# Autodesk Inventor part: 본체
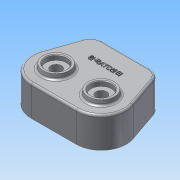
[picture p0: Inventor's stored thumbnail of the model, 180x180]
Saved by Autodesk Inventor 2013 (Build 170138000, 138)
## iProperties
Created: 2014-12
Part Number: 본체
Material: 알루미늄 6061
Document SubType Name: Modeling
Designer: Administrator
Density: 2.71 g/cm^3
Mass: 612.316 g
Surface Area: 666.735 cm^2
Volume: 225.947 cm^3
Author: Administrator
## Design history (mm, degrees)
sketch "스케치1"
  geometry: L1 (-47, 36)-(47, 36); L2 (47, 36)-(66.565, -20.803); L3 (32.527, -68.527)-(-32.527, -68.527); L4 (-66.565, -20.803)-(-47, 36); L5 (0, 0)-(-32.527, -32.527); L6 (0, 0)-(32.527, -32.527); A1 r 36 centre (-32.527, -32.527) between (-66.565, -20.803) and (-32.527, -68.527); A2 r 36 centre (32.527, -32.527) between (32.527, -68.527) and (66.565, -20.803); 2 further points
  constraints: 12 end point, 4 point on circle, 4 tangent, 2 centre point, 2 midpoint, 2 perpendicular, 2 vertical alignment, 1 horizontal, 1 parallel
  dimensions: "d0" = 94 distance of L1.start L1.end; "d89" = 72 diameter of A1; "d90" = 72 diameter of A2; "d91" = 36 distance from line of L1 L5.start; "d92" = 46 distance of L5.start L5.end
extrude "돌출1" new body sketch "스케치1" distance "d30" = 44; taper "d31" = 0 deg
fillet "모깎기2" dims "d33" = 18
sketch "스케치13"
  geometry: L1 (-34.162, 36)-(34.162, 36) reference; L2 (51.181, 23.862)-(66.565, -20.803) reference; L3 (-66.565, -20.803)-(-51.181, 23.862) reference; L4 (-34.162, 36)-(34.162, 36) reference; L5 (32.527, -68.527)-(-32.527, -68.527) reference; A1 r 18 centre (-34.162, 18) between (-34.162, 36) and (-51.181, 23.862) reference; A2 r 18 centre (34.162, 18) between (51.181, 23.862) and (34.162, 36) reference; A3 r 36 centre (32.527, -32.527) between (32.527, -68.527) and (66.565, -20.803) reference; A4 r 36 centre (-32.527, -32.527) between (-66.565, -20.803) and (-32.527, -68.527) reference; 2 further points
  constraints: 1 vertical alignment, 1 other
  dimensions: "d86" = 30 distance from line of L1 point (0, 6)
feature "엠보싱1" sketch "스케치13" dims "d0" = 94, "d87" = 1, "d88" = 0, "d89" = 72, "d90" = 72, "d91" = 36, "d92" = 46
sketch "스케치14"
  geometry: L1 (-51.181, 23.862)-(-66.565, -20.803) reference; L2 (-32.527, -68.527)-(32.527, -68.527) reference; L3 (66.565, -20.803)-(51.181, 23.862) reference; L4 (34.162, 36)-(-34.162, 36) reference; L5 (-46.453, 22.233)-(-61.837, -22.432); L6 (-32.527, -63.527)-(32.527, -63.527); L7 (61.837, -22.432)-(46.453, 22.233); L8 (34.162, 31)-(-34.162, 31); A1 r 18 centre (-34.162, 18) between (-34.162, 36) and (-51.181, 23.862) reference; A2 r 36 centre (-32.527, -32.527) between (-66.565, -20.803) and (-32.527, -68.527) reference; A3 r 36 centre (32.527, -32.527) between (32.527, -68.527) and (66.565, -20.803) reference; A4 r 18 centre (34.162, 18) between (51.181, 23.862) and (34.162, 36) reference; A5 r 13 centre (-34.162, 18) between (-34.162, 31) and (-46.453, 22.233); A6 r 31 centre (-32.527, -32.527) between (-61.837, -22.432) and (-32.527, -63.527); A7 r 31 centre (32.527, -32.527) between (32.527, -63.527) and (61.837, -22.432); A8 r 13 centre (34.162, 18) between (46.453, 22.233) and (34.162, 31); 1 further point
  constraints: 8 end point, 8 point on circle, 4 centre point, 7 other
  dimensions: "d93" = 5 distance between parallel lines of L4 L8
extrude "돌출8" cut sketch "스케치14" distance "d94" = 34; taper "d95" = 0 deg
sketch "스케치15"
  geometry: C1 r 24 at (0, 0); C2 r 24 at (-32.527, -32.527); C3 r 24 at (32.527, -32.527); A1 r 31 centre (-32.527, -32.527) between (-61.837, -22.432) and (-32.527, -63.527) reference; A2 r 31 centre (32.527, -32.527) between (32.527, -63.527) and (61.837, -22.432) reference; 1 further point
  constraints: 3 centre point, 3 coincident
  dimensions: "d96" = 48 diameter of C1; "d97" = 48 diameter of C2; "d98" = 48 diameter of C3
extrude "돌출9" join sketch "스케치15" distance "d99" = 11; taper "d100" = 0 deg
sketch "스케치16"
  geometry: C1 r 20 at (0, 0); A1 r 24 centre (0, 0) between (21.111, -11.416) and (-21.111, -11.416) reference
  constraints: 1 centre point, 1 coincident
  dimensions: "d101" = 40 diameter of C1
extrude "돌출10" cut sketch "스케치16" distance "d102" = 12; taper "d103" = 0 deg
sketch "스케치17"
  geometry: C1 r 20 at (0, 0) reference; C2 r 10 at (0, 0)
  constraints: 1 centre point, 1 coincident
  dimensions: "d104" = 20 diameter of C2
extrude "돌출11" cut sketch "스케치17" distance "d105" = 3; taper "d106" = 0 deg
sketch "스케치18"
  geometry: C1 r 20 at (0, 0) reference; C2 r 17.5 at (-32.527, -32.527); C3 r 17.5 at (32.527, -32.527); A1 r 24 centre (0, 0) between (-11.416, -21.111) and (11.416, -21.111) reference; A2 r 24 centre (32.527, -32.527) between (11.416, -21.111) and (21.111, -11.416) reference; A3 r 24 centre (0, 0) between (21.111, -11.416) and (-21.111, -11.416) reference; A4 r 24 centre (-32.527, -32.527) between (-21.111, -11.416) and (-11.416, -21.111) reference
  constraints: 2 centre point, 2 coincident
  dimensions: "d107" = 35 diameter of C2; "d108" = 35 diameter of C3
extrude "돌출12" cut sketch "스케치18" distance "d109" = 11; taper "d110" = 0 deg
sketch "스케치19"
  geometry: C1 r 20 at (-32.527, -32.527); C2 r 20 at (32.527, -32.527); A1 r 36 centre (-32.527, -32.527) between (-66.565, -20.803) and (-32.527, -68.527) reference; A2 r 36 centre (32.527, -32.527) between (32.527, -68.527) and (66.565, -20.803) reference; 1 further point
  constraints: 2 centre point, 2 coincident
  dimensions: "d111" = 40 diameter of C1; "d112" = 40 diameter of C2
extrude "돌출13" join sketch "스케치19" distance "d113" = 7; taper "d114" = -10 deg
sketch "스케치20"
  geometry: C1 r 18.766 at (0, 0) reference; C2 r 18.766 at (65.054, 0) reference; 3 further points
  constraints: 2 coincident
hole "구멍4" sketch "스케치20" at (0, 0), (65.054, 0) diameter "d115" = 15.5; stored, may be unused: countersink angle "d119" = 90 deg, drill point angle "d121" = 118 deg; dims "d116" = 20, "d117" = 30, "d118" = 7, "d120" = 23
sketch "스케치21"
  geometry: L1 (-61.837, -22.432)-(-46.453, 22.233) reference; L2 (46.453, 22.233)-(61.837, -22.432) reference; L3 (32.527, -63.527)-(-32.527, -63.527) reference; L4 (34.162, 36)-(-34.162, 36) reference; A1 r 8 centre (-51.7, 7) between (-54.305, -0.564) and (-49.095, 14.564); A2 r 8 centre (51.7, 7) between (49.095, 14.564) and (54.305, -0.564); A3 r 8 centre (0, -63.527) between (8, -63.527) and (-8, -63.527); 1 further point
  constraints: 8 point on line, 6 point on circle, 3 centre point, 1 horizontal alignment, 1 midpoint
  dimensions: "d122" = 16 diameter of A1; "d123" = 16 diameter of A2; "d124" = 29 distance from line of L4 A1.centre; "d125" = 16 diameter of A3
extrude "돌출14" join sketch "스케치21" stored distance "d126" = 7; taper "d127" = 0 deg
sketch "스케치22"
  geometry: A1 r 8 centre (-51.7, 7) between (-54.305, -0.564) and (-49.095, 14.564) reference; A2 r 8 centre (51.7, 7) between (49.095, 14.564) and (54.305, -0.564) reference; A3 r 8 centre (0, -63.527) between (8, -63.527) and (-8, -63.527) reference; 4 further points
  constraints: 3 coincident
hole "구멍5" sketch "스케치22" at (-51.7, 7), (51.7, 7), (0, -63.527) diameter "d128" = 4.959; stored, may be unused: countersink angle "d132" = 90 deg, drill point angle "d134" = 118 deg; dims "d129" = 20, "d130" = 30, "d131" = 7, "d133" = 23
fillet "모깎기3" dims "d135" = 3
fillet "모깎기4" dims "d136" = 3
fillet "모깎기5" dims "d137" = 0.1
chamfer "모따기1" distance "d138" = 1; stored, may be unused: second distance "d139" = 2, angle "d140" = 45 deg
fillet "모깎기6" dims "d141" = 0.3
node "솔리드1"
node "투영된 루프1"
node "투영된 루프2"
node "절단 모서리 투영4"
